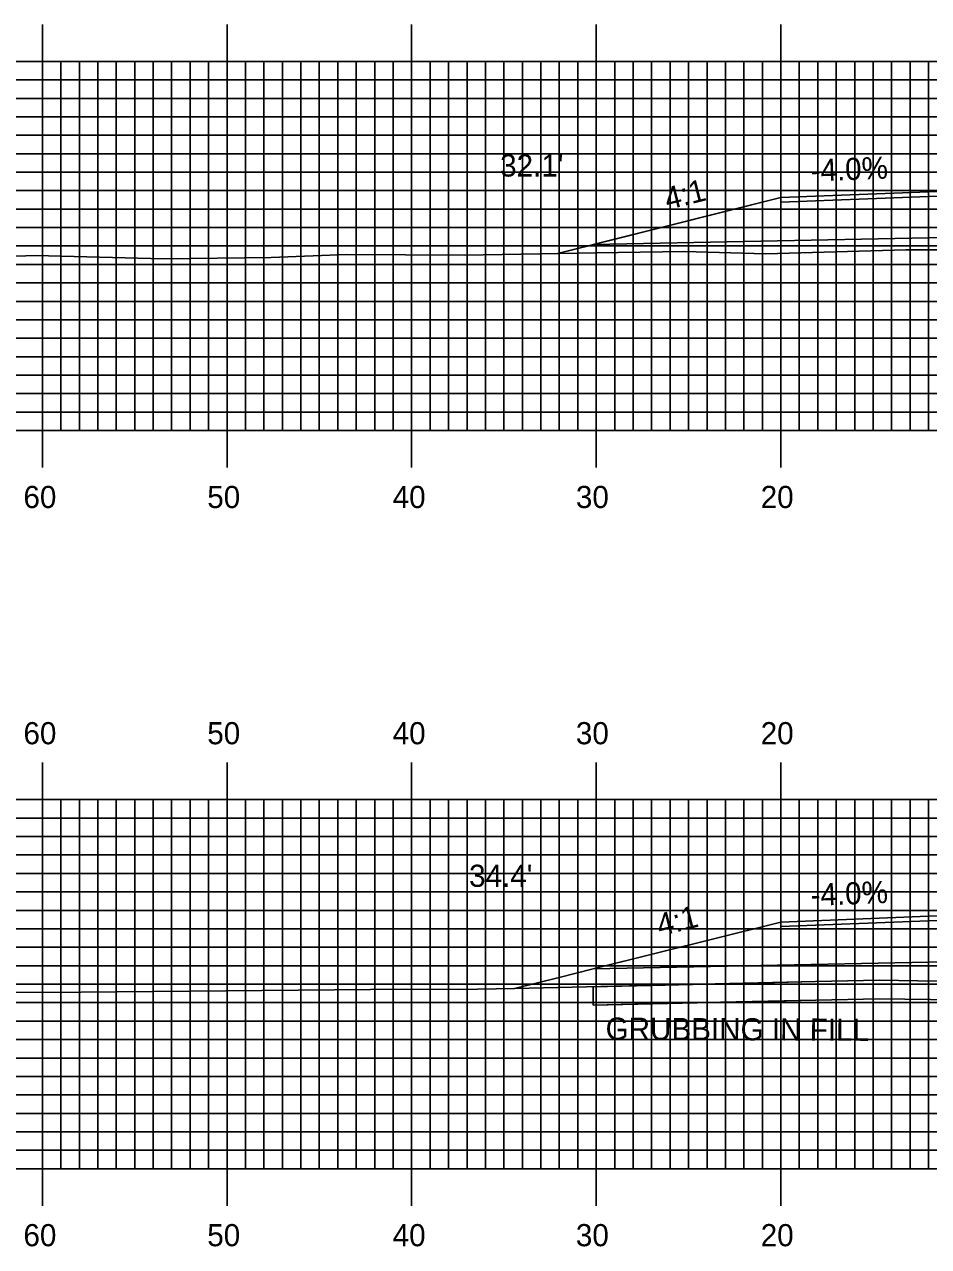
# Model space of a CAD drawing. Extents: x 1774383 to 1774727, y 442591 to 442811.
# Drawn here: x 1774488.2 to 1774537.2, y 442689.4 to 442755.7 of the extents above; entities that cross this region are included whole.
import ezdxf

# ---------------------------------------------------------------- set-up
doc = ezdxf.new("R2010")
doc.units = 0
for name, color, linetype in [('ANNOTATION', 7, 'Continuous'), ('D_Roadway_Centerline', 7, 'Continuous'), ('D_Roadway_Edge_Shoulder', 7, 'Continuous'), ('D_Roadway_SlopeLines', 7, 'Continuous'), ('D_Roadway_SubGrade', 7, 'Continuous'), ('D_Text_Standard', 7, 'Continuous'), ('GRUBBING IN FILL', 7, 'Continuous'), ('H_V ANNOTATION', 7, 'Continuous'), ('MAJOR', 7, 'Continuous'), ('MINOR', 7, 'Continuous'), ('S_Roadway_Centerline', 7, 'Continuous')]:
    doc.layers.add(name, color=color, linetype=linetype)

msp = doc.modelspace()

# ---------------------------------------------------------------- linework, layer by layer
at = {"layer": 'D_Roadway_Centerline'}
for points in [[(1774517.069, 442743.258), (1774518.981, 442743.736), (1774518.998, 442743.74), (1774519.832, 442743.949), (1774529.172, 442746.284), (1774537.172, 442746.604), (1774538.705, 442746.635), (1774549.172, 442746.844), (1774556.935, 442746.689), (1774561.172, 442746.604), (1774569.172, 442746.284), (1774579.347, 442743.74), (1774580.365, 442743.486)], [(1774514.75, 442703.428), (1774517.172, 442704.034), (1774518.998, 442704.49), (1774521.759, 442705.181), (1774529.172, 442707.034), (1774537.172, 442707.354), (1774537.174, 442707.354), (1774549.172, 442707.594), (1774551.354, 442707.551), (1774561.173, 442707.354), (1774565.061, 442707.199), (1774569.172, 442707.034), (1774573.892, 442705.854), (1774579.346, 442704.49), (1774584.264, 442703.261)]]:
    msp.add_lwpolyline(points, dxfattribs=at)
at = {"layer": 'D_Roadway_Edge_Shoulder'}
for points in [[(1774537.172, 442746.604), (1774529.172, 442746.284), (1774529.172, 442746.034), (1774537.172, 442746.354)], [(1774537.172, 442707.354), (1774529.172, 442707.034), (1774529.172, 442706.784), (1774537.172, 442707.104)]]:
    msp.add_lwpolyline(points, close=True, dxfattribs=at)
at = {"layer": 'D_Roadway_SlopeLines'}
for points in [[(1774529.172, 442746.284), (1774517.069, 442743.258)], [(1774529.172, 442707.034), (1774518.998, 442704.49), (1774517.172, 442704.034), (1774514.75, 442703.428)]]:
    msp.add_lwpolyline(points, dxfattribs=at)
at = {"layer": 'D_Roadway_SubGrade'}
for points in [[(1774537.172, 442744.104), (1774518.998, 442743.74), (1774529.172, 442746.284), (1774529.172, 442746.034), (1774537.172, 442746.354), (1774549.172, 442746.594), (1774561.172, 442746.354), (1774569.172, 442746.034), (1774569.172, 442746.284), (1774579.347, 442743.74), (1774561.172, 442744.104), (1774549.172, 442744.344)], [(1774537.172, 442704.854), (1774518.998, 442704.49), (1774529.172, 442707.034), (1774529.172, 442706.784), (1774537.172, 442707.104), (1774549.172, 442707.344), (1774561.172, 442707.104), (1774569.172, 442706.784), (1774569.172, 442707.034), (1774579.346, 442704.49), (1774561.172, 442704.854), (1774549.172, 442705.094)]]:
    msp.add_lwpolyline(points, close=True, dxfattribs=at)
at = {"layer": 'GRUBBING IN FILL'}
msp.add_line((1774518.998, 442703.527), (1774518.998, 442702.527), dxfattribs=at)
msp.add_line((1774518.998, 442703.527), (1774518.998, 442702.527), dxfattribs=at)
msp.add_lwpolyline([(1774518.998, 442702.527), (1774525.033, 442702.668), (1774531.069, 442702.808), (1774534.516, 442702.875), (1774538.645, 442702.811), (1774546.521, 442702.599), (1774549.172, 442702.486), (1774549.172, 442703.487), (1774546.555, 442703.599), (1774542.611, 442703.705), (1774538.666, 442703.811), (1774534.514, 442703.875), (1774532.781, 442703.841), (1774531.048, 442703.808), (1774522.901, 442703.618), (1774518.998, 442703.527)], close=True, dxfattribs=at)
msp.add_lwpolyline([(1774518.998, 442702.527), (1774525.033, 442702.668), (1774531.069, 442702.808), (1774534.516, 442702.875), (1774538.645, 442702.811), (1774546.521, 442702.599), (1774549.172, 442702.486), (1774549.172, 442703.487), (1774546.555, 442703.599), (1774542.611, 442703.705), (1774538.666, 442703.811), (1774534.514, 442703.875), (1774532.781, 442703.841), (1774531.048, 442703.808), (1774522.901, 442703.618), (1774518.998, 442703.527)], close=True, dxfattribs=at)
msp.add_lwpolyline([(1774518.998, 442702.527), (1774531.069, 442702.808), (1774534.516, 442702.875), (1774538.645, 442702.811), (1774546.521, 442702.599), (1774554.212, 442702.272), (1774562.28, 442702.041), (1774569.699, 442702.12), (1774576.489, 442702.142), (1774579.346, 442702.216)], dxfattribs=at)
msp.add_lwpolyline([(1774518.998, 442702.527), (1774531.069, 442702.808), (1774534.516, 442702.875), (1774538.645, 442702.811), (1774546.521, 442702.599), (1774554.212, 442702.272), (1774562.28, 442702.041), (1774569.699, 442702.12), (1774576.489, 442702.142), (1774579.346, 442702.216)], dxfattribs=at)
at = {"layer": 'MAJOR'}
for p, q in [((1774489.172, 442755.669), (1774489.172, 442753.665)), ((1774499.172, 442755.669), (1774499.172, 442753.665)), ((1774509.172, 442755.669), (1774509.172, 442753.665)), ((1774519.172, 442755.669), (1774519.172, 442753.665)), ((1774529.172, 442755.669), (1774529.172, 442753.665)), ((1774409.172, 442753.665), (1774689.172, 442753.665)), ((1774409.172, 442753.665), (1774689.172, 442753.665)), ((1774489.172, 442733.665), (1774489.172, 442753.665)), ((1774499.172, 442733.665), (1774499.172, 442753.665)), ((1774509.172, 442733.665), (1774509.172, 442753.665)), ((1774519.172, 442733.665), (1774519.172, 442753.665)), ((1774529.172, 442733.665), (1774529.172, 442753.665)), ((1774409.172, 442748.665), (1774689.172, 442748.665)), ((1774409.172, 442743.665), (1774689.172, 442743.665)), ((1774409.172, 442738.665), (1774689.172, 442738.665)), ((1774409.172, 442733.665), (1774689.172, 442733.665)), ((1774409.172, 442733.665), (1774689.172, 442733.665)), ((1774489.172, 442731.661), (1774489.172, 442733.665)), ((1774499.172, 442731.661), (1774499.172, 442733.665)), ((1774509.172, 442731.661), (1774509.172, 442733.665)), ((1774519.172, 442731.661), (1774519.172, 442733.665)), ((1774529.172, 442731.661), (1774529.172, 442733.665)), ((1774489.172, 442715.669), (1774489.172, 442713.665)), ((1774499.172, 442715.669), (1774499.172, 442713.665)), ((1774509.172, 442715.669), (1774509.172, 442713.665)), ((1774519.172, 442715.669), (1774519.172, 442713.665)), ((1774529.172, 442715.669), (1774529.172, 442713.665)), ((1774409.172, 442713.665), (1774689.172, 442713.665)), ((1774409.172, 442713.665), (1774689.172, 442713.665)), ((1774489.172, 442693.665), (1774489.172, 442713.665)), ((1774499.172, 442693.665), (1774499.172, 442713.665)), ((1774509.172, 442693.665), (1774509.172, 442713.665)), ((1774519.172, 442693.665), (1774519.172, 442713.665)), ((1774529.172, 442693.665), (1774529.172, 442713.665)), ((1774409.172, 442708.665), (1774689.172, 442708.665)), ((1774409.172, 442703.665), (1774689.172, 442703.665)), ((1774409.172, 442698.665), (1774689.172, 442698.665)), ((1774409.172, 442693.665), (1774689.172, 442693.665)), ((1774409.172, 442693.665), (1774689.172, 442693.665)), ((1774489.172, 442691.661), (1774489.172, 442693.665)), ((1774499.172, 442691.661), (1774499.172, 442693.665)), ((1774509.172, 442691.661), (1774509.172, 442693.665)), ((1774519.172, 442691.661), (1774519.172, 442693.665)), ((1774529.172, 442691.661), (1774529.172, 442693.665))]:
    msp.add_line(p, q, dxfattribs=at)
at = {"layer": 'MINOR'}
for p, q in [((1774490.172, 442733.665), (1774490.172, 442753.665)), ((1774491.172, 442733.665), (1774491.172, 442753.665)), ((1774492.172, 442733.665), (1774492.172, 442753.665)), ((1774493.172, 442733.665), (1774493.172, 442753.665)), ((1774494.172, 442733.665), (1774494.172, 442753.665)), ((1774495.172, 442733.665), (1774495.172, 442753.665)), ((1774496.172, 442733.665), (1774496.172, 442753.665)), ((1774497.172, 442733.665), (1774497.172, 442753.665)), ((1774498.172, 442733.665), (1774498.172, 442753.665)), ((1774500.172, 442733.665), (1774500.172, 442753.665)), ((1774501.172, 442733.665), (1774501.172, 442753.665)), ((1774502.172, 442733.665), (1774502.172, 442753.665)), ((1774503.172, 442733.665), (1774503.172, 442753.665)), ((1774504.172, 442733.665), (1774504.172, 442753.665)), ((1774505.172, 442733.665), (1774505.172, 442753.665)), ((1774506.172, 442733.665), (1774506.172, 442753.665)), ((1774507.172, 442733.665), (1774507.172, 442753.665)), ((1774508.172, 442733.665), (1774508.172, 442753.665)), ((1774510.172, 442733.665), (1774510.172, 442753.665)), ((1774511.172, 442733.665), (1774511.172, 442753.665)), ((1774512.172, 442733.665), (1774512.172, 442753.665)), ((1774513.172, 442733.665), (1774513.172, 442753.665)), ((1774514.172, 442733.665), (1774514.172, 442753.665)), ((1774515.172, 442733.665), (1774515.172, 442753.665)), ((1774516.172, 442733.665), (1774516.172, 442753.665)), ((1774517.172, 442733.665), (1774517.172, 442753.665)), ((1774518.172, 442733.665), (1774518.172, 442753.665)), ((1774520.172, 442733.665), (1774520.172, 442753.665)), ((1774521.172, 442733.665), (1774521.172, 442753.665)), ((1774522.172, 442733.665), (1774522.172, 442753.665)), ((1774523.172, 442733.665), (1774523.172, 442753.665)), ((1774524.172, 442733.665), (1774524.172, 442753.665)), ((1774525.172, 442733.665), (1774525.172, 442753.665)), ((1774526.172, 442733.665), (1774526.172, 442753.665)), ((1774527.172, 442733.665), (1774527.172, 442753.665)), ((1774528.172, 442733.665), (1774528.172, 442753.665)), ((1774530.172, 442733.665), (1774530.172, 442753.665)), ((1774531.172, 442733.665), (1774531.172, 442753.665)), ((1774532.172, 442733.665), (1774532.172, 442753.665)), ((1774533.172, 442733.665), (1774533.172, 442753.665)), ((1774534.172, 442733.665), (1774534.172, 442753.665)), ((1774535.172, 442733.665), (1774535.172, 442753.665)), ((1774536.172, 442733.665), (1774536.172, 442753.665)), ((1774537.172, 442733.665), (1774537.172, 442753.665)), ((1774409.172, 442752.665), (1774689.172, 442752.665)), ((1774409.172, 442751.665), (1774689.172, 442751.665)), ((1774409.172, 442750.665), (1774689.172, 442750.665)), ((1774409.172, 442749.665), (1774689.172, 442749.665)), ((1774409.172, 442747.665), (1774689.172, 442747.665)), ((1774409.172, 442746.665), (1774689.172, 442746.665)), ((1774409.172, 442745.665), (1774689.172, 442745.665)), ((1774409.172, 442744.665), (1774689.172, 442744.665)), ((1774409.172, 442742.665), (1774689.172, 442742.665)), ((1774409.172, 442741.665), (1774689.172, 442741.665)), ((1774409.172, 442740.665), (1774689.172, 442740.665)), ((1774409.172, 442739.665), (1774689.172, 442739.665)), ((1774409.172, 442737.665), (1774689.172, 442737.665)), ((1774409.172, 442736.665), (1774689.172, 442736.665)), ((1774409.172, 442735.665), (1774689.172, 442735.665)), ((1774409.172, 442734.665), (1774689.172, 442734.665)), ((1774490.172, 442693.665), (1774490.172, 442713.665)), ((1774491.172, 442693.665), (1774491.172, 442713.665)), ((1774492.172, 442693.665), (1774492.172, 442713.665)), ((1774493.172, 442693.665), (1774493.172, 442713.665)), ((1774494.172, 442693.665), (1774494.172, 442713.665)), ((1774495.172, 442693.665), (1774495.172, 442713.665)), ((1774496.172, 442693.665), (1774496.172, 442713.665)), ((1774497.172, 442693.665), (1774497.172, 442713.665)), ((1774498.172, 442693.665), (1774498.172, 442713.665)), ((1774500.172, 442693.665), (1774500.172, 442713.665)), ((1774501.172, 442693.665), (1774501.172, 442713.665)), ((1774502.172, 442693.665), (1774502.172, 442713.665)), ((1774503.172, 442693.665), (1774503.172, 442713.665)), ((1774504.172, 442693.665), (1774504.172, 442713.665)), ((1774505.172, 442693.665), (1774505.172, 442713.665)), ((1774506.172, 442693.665), (1774506.172, 442713.665)), ((1774507.172, 442693.665), (1774507.172, 442713.665)), ((1774508.172, 442693.665), (1774508.172, 442713.665)), ((1774510.172, 442693.665), (1774510.172, 442713.665)), ((1774511.172, 442693.665), (1774511.172, 442713.665)), ((1774512.172, 442693.665), (1774512.172, 442713.665)), ((1774513.172, 442693.665), (1774513.172, 442713.665)), ((1774514.172, 442693.665), (1774514.172, 442713.665)), ((1774515.172, 442693.665), (1774515.172, 442713.665)), ((1774516.172, 442693.665), (1774516.172, 442713.665)), ((1774517.172, 442693.665), (1774517.172, 442713.665)), ((1774518.172, 442693.665), (1774518.172, 442713.665)), ((1774520.172, 442693.665), (1774520.172, 442713.665)), ((1774521.172, 442693.665), (1774521.172, 442713.665)), ((1774522.172, 442693.665), (1774522.172, 442713.665)), ((1774523.172, 442693.665), (1774523.172, 442713.665)), ((1774524.172, 442693.665), (1774524.172, 442713.665)), ((1774525.172, 442693.665), (1774525.172, 442713.665)), ((1774526.172, 442693.665), (1774526.172, 442713.665)), ((1774527.172, 442693.665), (1774527.172, 442713.665)), ((1774528.172, 442693.665), (1774528.172, 442713.665)), ((1774530.172, 442693.665), (1774530.172, 442713.665)), ((1774531.172, 442693.665), (1774531.172, 442713.665)), ((1774532.172, 442693.665), (1774532.172, 442713.665)), ((1774533.172, 442693.665), (1774533.172, 442713.665)), ((1774534.172, 442693.665), (1774534.172, 442713.665)), ((1774535.172, 442693.665), (1774535.172, 442713.665)), ((1774536.172, 442693.665), (1774536.172, 442713.665)), ((1774537.172, 442693.665), (1774537.172, 442713.665)), ((1774409.172, 442712.665), (1774689.172, 442712.665)), ((1774409.172, 442711.665), (1774689.172, 442711.665)), ((1774409.172, 442710.665), (1774689.172, 442710.665)), ((1774409.172, 442709.665), (1774689.172, 442709.665)), ((1774409.172, 442707.665), (1774689.172, 442707.665)), ((1774409.172, 442706.665), (1774689.172, 442706.665)), ((1774409.172, 442705.665), (1774689.172, 442705.665)), ((1774409.172, 442704.665), (1774689.172, 442704.665)), ((1774409.172, 442702.665), (1774689.172, 442702.665)), ((1774409.172, 442701.665), (1774689.172, 442701.665)), ((1774409.172, 442700.665), (1774689.172, 442700.665)), ((1774409.172, 442699.665), (1774689.172, 442699.665)), ((1774409.172, 442697.665), (1774689.172, 442697.665)), ((1774409.172, 442696.665), (1774689.172, 442696.665)), ((1774409.172, 442695.665), (1774689.172, 442695.665)), ((1774409.172, 442694.665), (1774689.172, 442694.665))]:
    msp.add_line(p, q, dxfattribs=at)
at = {"layer": 'S_Roadway_Centerline'}
for points in [[(1774476.385, 442742.731), (1774488.815, 442743.149), (1774495.737, 442742.975), (1774501.567, 442743.041), (1774505.644, 442743.206), (1774512.039, 442743.175), (1774519.175, 442743.293), (1774523.952, 442743.363), (1774528.363, 442743.241), (1774535.941, 442743.448), (1774544.165, 442743.454), (1774548.194, 442743.476), (1774551.667, 442743.416), (1774558.671, 442743.503), (1774566.948, 442743.394), (1774574.166, 442743.552), (1774591.672, 442743.364), (1774594.434, 442743.266)], [(1774485.788, 442703.221), (1774491.276, 442703.231), (1774508.898, 442703.401), (1774511.723, 442703.371), (1774514.755, 442703.428), (1774531.048, 442703.808), (1774534.514, 442703.875), (1774538.666, 442703.811), (1774546.555, 442703.599), (1774554.247, 442703.271), (1774562.289, 442703.041), (1774569.692, 442703.12), (1774576.475, 442703.142), (1774581.467, 442703.272), (1774586.892, 442703.25), (1774593.584, 442703.419), (1774600.43, 442703.939)]]:
    msp.add_lwpolyline(points, dxfattribs=at)

# ---------------------------------------------------------------- texts
at = {"layer": 'ANNOTATION'}
for s, rotation, p in [('-4.0%', 2.29053, (1774530.804, 442747.151)), ('4:1', 14.0382, (1774523.037, 442745.612)), ('-4.0%', 2.29053, (1774530.804, 442707.901)), ('4:1', 14.03916, (1774522.621, 442706.258))]:
    msp.add_text(s, height=1.2, rotation=rotation, dxfattribs=at).set_placement(p)
at = {"layer": 'D_Text_Standard'}
for s, p in [("32.1'", (1774513.966, 442747.427)), ("34.4'", (1774512.284, 442708.939))]:
    msp.add_text(s, height=1.2, dxfattribs=at).set_placement(p)
at = {"layer": 'GRUBBING IN FILL'}
msp.add_text('GRUBBING IN FILL', height=1.2, rotation=359.74859, dxfattribs=at).set_placement((1774519.677, 442700.656))
at = {"layer": 'H_V ANNOTATION'}
for s, p in [('60', (1774488.144, 442729.465)), ('50', (1774498.101, 442729.465)), ('40', (1774508.144, 442729.465)), ('30', (1774518.069, 442729.465)), ('20', (1774528.08, 442729.465)), ('60', (1774488.144, 442716.665)), ('50', (1774498.101, 442716.665)), ('40', (1774508.144, 442716.665)), ('30', (1774518.069, 442716.665)), ('20', (1774528.08, 442716.665)), ('60', (1774488.144, 442689.465)), ('50', (1774498.101, 442689.465)), ('40', (1774508.144, 442689.465)), ('30', (1774518.069, 442689.465)), ('20', (1774528.08, 442689.465))]:
    msp.add_text(s, height=1.2, dxfattribs=at).set_placement(p)

doc.saveas('drawing.dxf')
